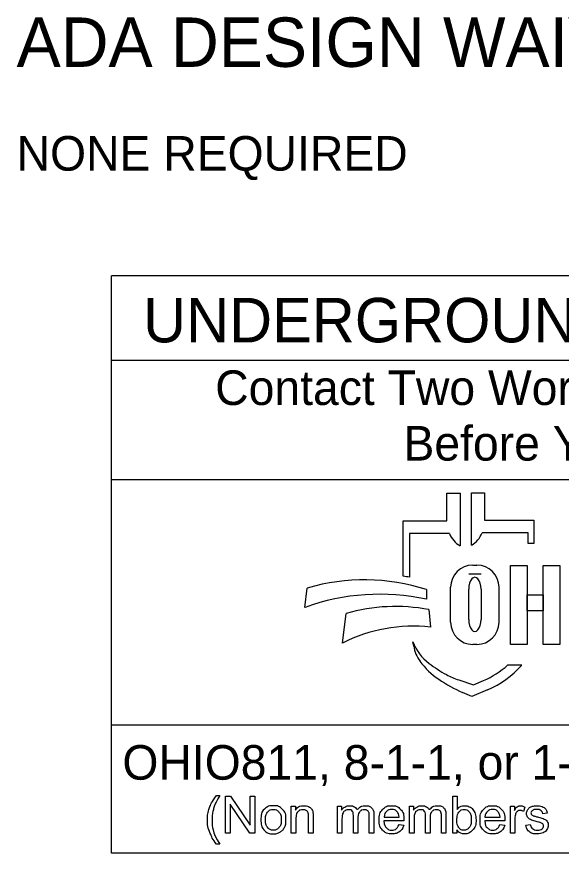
# Model space of a CAD drawing. Extents: x 0 to 64.8, y -5 to 22.
# Drawn here: x 1.995 to 4.196, y 2.143 to 5.529 of the extents above; entities that cross this region are included whole.
import ezdxf

# ---------------------------------------------------------------- set-up
doc = ezdxf.new("R2010")
doc.units = 0
doc.layers.add('SH_Data', color=7, linetype='Continuous')
doc.layers.add('SH_Text', color=7, linetype='Continuous')

msp = doc.modelspace()

# ---------------------------------------------------------------- linework, layer by layer
at = {"layer": 'SH_Data'}
for p, q in [((2.3775, 2.1428), (2.3775, 4.4803)), ((6.6275, 4.4803), (2.3775, 4.4803)), ((2.3775, 4.1387), (6.6275, 4.1387)), ((2.3775, 3.6553), (6.6275, 3.6553)), ((6.6275, 2.6607), (2.3775, 2.6607)), ((6.6275, 2.1428), (2.3775, 2.1428))]:
    msp.add_line(p, q, dxfattribs=at)
at = {"layer": 'SH_Text'}
for p, q in [((3.7335, 3.4883), (3.7335, 3.5998)), ((3.7335, 3.5998), (3.7872, 3.5998)), ((3.7872, 3.5998), (3.7872, 3.3877)), ((3.8329, 3.39), (3.8329, 3.6021)), ((3.8329, 3.6021), (3.8865, 3.6021)), ((3.8865, 3.6021), (3.8865, 3.4906)), ((3.5576, 3.2644), (3.5576, 3.4883)), ((3.5576, 3.4883), (3.7335, 3.4883)), ((3.8865, 3.4906), (4.0857, 3.4906)), ((4.0857, 3.4906), (4.0857, 3.3968)), ((3.5828, 3.4369), (3.5828, 3.26)), ((3.7439, 3.4369), (3.5828, 3.4369)), ((4.0625, 3.4392), (3.8761, 3.4392)), ((4.0625, 3.3968), (4.0625, 3.4392)), ((4.0857, 3.3968), (4.0625, 3.3968)), ((3.8385, 3.3091), (3.8551, 3.3091)), ((3.8718, 3.2721), (3.822, 3.2721)), ((3.7491, 3.0776), (3.7491, 3.2196)), ((3.9445, 3.2196), (3.9445, 3.0776)), ((3.1602, 3.1381), (3.1696, 3.2162)), ((3.6509, 3.2097), (3.6509, 3.1709)), ((3.822, 3.089), (3.822, 3.2114)), ((3.8718, 3.2114), (3.8718, 3.089)), ((3.6608, 3.1291), (3.6671, 3.0582)), ((3.312, 2.9936), (3.3267, 3.1137)), ((3.5997, 2.9807), (3.5967, 2.9986)), ((3.8551, 2.9882), (3.8385, 2.9882)), ((3.98, 2.9048), (4.0375, 2.9048)), ((3.7816, 2.8444), (3.841, 2.8239)), ((3.841, 2.8239), (3.8821, 2.8417)), ((3.835, 2.7769), (3.7976, 2.7934)), ((3.8983, 2.8044), (3.835, 2.7769))]:
    msp.add_line(p, q, dxfattribs=at)
for points in [[(3.991, 3.3081), (4.0589, 3.3081), (4.0589, 2.9881), (3.991, 2.9881)], [(4.1231, 3.3081), (4.1911, 3.3081), (4.1911, 2.9881), (4.1231, 2.9881)], [(4.0589, 3.1882), (4.1231, 3.1882), (4.1231, 3.1242), (4.0589, 3.1242)]]:
    msp.add_lwpolyline(points, close=True, dxfattribs=at)
for points in [[(2.8021, 2.3766), (2.8153, 2.3766)], [(2.8389, 2.2239), (2.8389, 2.3741), (2.8592, 2.3741), (2.9382, 2.2561), (2.9382, 2.3741), (2.9572, 2.3741), (2.9572, 2.2239), (2.9369, 2.2239), (2.8579, 2.3419), (2.8579, 2.2239), (2.8389, 2.2239)], [(3.7743, 2.2239), (3.7573, 2.2239), (3.7573, 2.3741), (3.7757, 2.3741), (3.7757, 2.3206)], [(3.1048, 2.2239), (3.1048, 2.3328), (3.1214, 2.3328), (3.1214, 2.3173)], [(3.2912, 2.2239), (3.2912, 2.3328), (3.3077, 2.3328), (3.3077, 2.3174)], [(3.5826, 2.2239), (3.5826, 2.3328), (3.5991, 2.3328), (3.5991, 2.3174)], [(3.9904, 2.2239), (3.9904, 2.3328), (4.007, 2.3328), (4.007, 2.3163)], [(4.0495, 2.3293), (4.043, 2.3122)], [(4.1394, 2.3046), (4.1213, 2.3022)], [(3.1233, 2.2833), (3.1233, 2.2239), (3.1048, 2.2239)], [(3.1932, 2.2908), (3.1932, 2.2239), (3.1748, 2.2239), (3.1748, 2.2901)], [(3.3097, 2.2803), (3.3097, 2.2239), (3.2912, 2.2239)], [(3.3743, 2.2871), (3.3743, 2.2239), (3.3559, 2.2239), (3.3559, 2.2946)], [(3.4388, 2.2986), (3.4388, 2.2239), (3.4203, 2.2239), (3.4203, 2.2924)], [(3.56, 2.2736), (3.4788, 2.2736)], [(3.4799, 2.2887), (3.5406, 2.2887)], [(3.601, 2.2803), (3.601, 2.2239), (3.5826, 2.2239)], [(3.6657, 2.2871), (3.6657, 2.2239), (3.6473, 2.2239), (3.6473, 2.2946)], [(3.7301, 2.2986), (3.7301, 2.2239), (3.7117, 2.2239), (3.7117, 2.2924)], [(3.968, 2.2736), (3.8868, 2.2736)], [(3.8879, 2.2887), (3.9486, 2.2887)], [(4.0088, 2.2809), (4.0088, 2.2239), (3.9904, 2.2239)], [(3.5404, 2.2591), (3.5595, 2.2567)], [(3.7743, 2.2375), (3.7743, 2.2239)], [(3.9484, 2.2591), (3.9675, 2.2567)], [(4.053, 2.2564), (4.0712, 2.2593)], [(2.8153, 2.1798), (2.8021, 2.1798)]]:
    msp.add_lwpolyline(points, dxfattribs=at)
for centre, radius, start, end in [((3.8353, 3.4736), 0.0985, 201.9296, 240.7469), ((3.7847, 3.476), 0.0985, 299.2531, 338.0704), ((3.8385, 3.2196), 0.0895, 90, 180), ((3.8551, 3.2196), 0.0895, 0, 90), ((3.4295, 2.4554), 0.8191, 79.2074, 81.0007), ((3.3997, 2.4302), 0.8191, 72.1402, 106.3144), ((3.4628, 2.2991), 0.8919, 77.8238, 109.8274), ((3.5267, 2.4094), 0.7322, 79.44, 105.8467), ((3.5987, 2.4262), 0.6357, 83.8248, 116.8021), ((3.8385, 3.0776), 0.0895, 180, 270), ((3.8551, 3.0776), 0.0895, 270, 0), ((3.7841, 3.0707), 0.2008, 201.0457, 232.5314), ((3.741, 3.0048), 0.1433, 189.6817, 216.0884), ((3.8747, 3.1022), 0.3088, 216.0884, 235.7167), ((3.9766, 3.3219), 0.5173, 232.5314, 241.794), ((3.7387, 3.1722), 0.3602, 293.4582, 312.0712), ((3.7387, 3.1722), 0.401, 293.4582, 317.8286), ((4.0412, 3.3465), 0.6044, 235.7167, 246.2325), ((3.8914, 3.1631), 0.3371, 241.794, 250.9821)]:
    msp.add_arc(centre, radius, start, end, dxfattribs=at)
for centre, start_param, end_param in [((3.8469, 3.2114), 4.712389, 7.853982), ((3.8469, 3.089), 1.570796, 4.712389)]:
    msp.add_ellipse(centre, major_axis=(0, 0.0484), ratio=0.514403, start_param=start_param, end_param=end_param, dxfattribs=at)
for points in [[(2.8021, 2.1798), (2.7869, 2.199), (2.7763, 2.2248), (2.7657, 2.2506), (2.7657, 2.2783), (2.7657, 2.3026), (2.7736, 2.325), (2.7829, 2.3509), (2.8021, 2.3766)], [(2.8153, 2.3766), (2.8029, 2.3553), (2.7989, 2.3462), (2.7927, 2.332), (2.7891, 2.3167), (2.7847, 2.2975), (2.7847, 2.2782), (2.7847, 2.2289), (2.8153, 2.1798)], [(2.9814, 2.2783), (2.9814, 2.3085), (2.9981, 2.3231), (3.0122, 2.3352), (3.0323, 2.3352), (3.0547, 2.3352), (3.069, 2.3205), (3.0832, 2.3058), (3.0832, 2.2799), (3.0832, 2.2589), (3.0769, 2.2469), (3.0706, 2.2348), (3.0586, 2.2282), (3.0466, 2.2215), (3.0323, 2.2215), (3.0095, 2.2215), (2.9954, 2.2362), (2.9814, 2.2508), (2.9814, 2.2783)], [(3.0003, 2.2783), (3.0003, 2.2574), (3.0094, 2.247), (3.0185, 2.2366), (3.0323, 2.2366), (3.046, 2.2366), (3.0551, 2.2471), (3.0642, 2.2575), (3.0642, 2.279), (3.0642, 2.2991), (3.0551, 2.3095), (3.0459, 2.3199), (3.0323, 2.3199), (3.0185, 2.3199), (3.0094, 2.3096), (3.0003, 2.2992), (3.0003, 2.2783)], [(3.1214, 2.3173), (3.1334, 2.3352), (3.156, 2.3352), (3.1659, 2.3352), (3.1741, 2.3316), (3.1823, 2.3281), (3.1864, 2.3224), (3.1905, 2.3166), (3.1922, 2.3087), (3.1932, 2.3036), (3.1932, 2.2908)], [(3.1748, 2.2901), (3.1748, 2.3013), (3.1726, 2.3069), (3.1705, 2.3125), (3.165, 2.3158), (3.1595, 2.3191), (3.1521, 2.3191), (3.1404, 2.3191), (3.1318, 2.3117), (3.1233, 2.3042), (3.1233, 2.2833)], [(3.3077, 2.3174), (3.3128, 2.3254), (3.3214, 2.3303), (3.3299, 2.3352), (3.3407, 2.3352), (3.3528, 2.3352), (3.3606, 2.3301), (3.3683, 2.3251), (3.3715, 2.3161), (3.3844, 2.3352), (3.4051, 2.3352), (3.4213, 2.3352), (3.43, 2.3262), (3.4388, 2.3172), (3.4388, 2.2986)], [(3.3559, 2.2946), (3.3559, 2.3069), (3.3514, 2.313), (3.3469, 2.3191), (3.3366, 2.3191), (3.3288, 2.3191), (3.3222, 2.315), (3.3156, 2.311), (3.3126, 2.3031), (3.3097, 2.2952), (3.3097, 2.2803)], [(3.4203, 2.2924), (3.4203, 2.3035), (3.4185, 2.3083), (3.4168, 2.3132), (3.412, 2.3162), (3.4073, 2.3191), (3.401, 2.3191), (3.3895, 2.3191), (3.3819, 2.3115), (3.3743, 2.3039), (3.3743, 2.2871)], [(3.5595, 2.2567), (3.555, 2.24), (3.5428, 2.2307), (3.5306, 2.2215), (3.5117, 2.2215), (3.4878, 2.2215), (3.4738, 2.2362), (3.4598, 2.2509), (3.4598, 2.2774), (3.4598, 2.3049), (3.474, 2.32), (3.4881, 2.3352), (3.5106, 2.3352), (3.5324, 2.3352), (3.5463, 2.3203), (3.5601, 2.3055), (3.5601, 2.2785), (3.5601, 2.2769), (3.56, 2.2736)], [(3.5406, 2.2887), (3.5394, 2.3025), (3.5337, 2.3094), (3.5249, 2.3201), (3.5108, 2.3201), (3.4981, 2.3201), (3.4894, 2.3115), (3.4808, 2.303), (3.4799, 2.2887)], [(3.5991, 2.3174), (3.6042, 2.3254), (3.6127, 2.3303), (3.6212, 2.3352), (3.6321, 2.3352), (3.6442, 2.3352), (3.6519, 2.3301), (3.6597, 2.3251), (3.6628, 2.3161), (3.6758, 2.3352), (3.6965, 2.3352), (3.7127, 2.3352), (3.7214, 2.3262), (3.7301, 2.3172), (3.7301, 2.2986)], [(3.6473, 2.2946), (3.6473, 2.3069), (3.6428, 2.313), (3.6383, 2.3191), (3.628, 2.3191), (3.6202, 2.3191), (3.6136, 2.315), (3.607, 2.311), (3.604, 2.3031), (3.601, 2.2952), (3.601, 2.2803)], [(3.7117, 2.2924), (3.7117, 2.3035), (3.7099, 2.3083), (3.7081, 2.3132), (3.7034, 2.3162), (3.6987, 2.3191), (3.6923, 2.3191), (3.6809, 2.3191), (3.6733, 2.3115), (3.6657, 2.3039), (3.6657, 2.2871)], [(3.7741, 2.2792), (3.7741, 2.2596), (3.7794, 2.2509), (3.7881, 2.2366), (3.8029, 2.2366), (3.815, 2.2366), (3.8238, 2.2471), (3.8326, 2.2576), (3.8326, 2.2784), (3.8326, 2.2998), (3.8241, 2.3099), (3.8157, 2.3201), (3.8038, 2.3201), (3.7917, 2.3201), (3.7829, 2.3096), (3.7741, 2.299), (3.7741, 2.2792)], [(3.7757, 2.3206), (3.7874, 2.3352), (3.8055, 2.3352), (3.8155, 2.3352), (3.8245, 2.3311), (3.8335, 2.3271), (3.8392, 2.3198), (3.845, 2.3124), (3.8483, 2.3021), (3.8516, 2.2918), (3.8516, 2.28), (3.8516, 2.252), (3.8378, 2.2368), (3.8239, 2.2215), (3.8046, 2.2215), (3.7853, 2.2215), (3.7743, 2.2375)], [(3.9675, 2.2567), (3.963, 2.24), (3.9508, 2.2307), (3.9386, 2.2215), (3.9196, 2.2215), (3.8958, 2.2215), (3.8818, 2.2362), (3.8678, 2.2509), (3.8678, 2.2774), (3.8678, 2.3049), (3.882, 2.32), (3.8961, 2.3352), (3.9186, 2.3352), (3.9404, 2.3352), (3.9543, 2.3203), (3.9681, 2.3055), (3.9681, 2.2785), (3.9681, 2.2769), (3.968, 2.2736)], [(3.9486, 2.2887), (3.9474, 2.3025), (3.9417, 2.3094), (3.9328, 2.3201), (3.9188, 2.3201), (3.9061, 2.3201), (3.8974, 2.3115), (3.8888, 2.303), (3.8879, 2.2887)], [(4.007, 2.3163), (4.0133, 2.3278), (4.0187, 2.3315), (4.0241, 2.3352), (4.0305, 2.3352), (4.0398, 2.3352), (4.0495, 2.3293)], [(4.043, 2.3122), (4.0363, 2.3162), (4.0295, 2.3162), (4.0235, 2.3162), (4.0187, 2.3125), (4.0139, 2.3089), (4.0119, 2.3024), (4.0088, 2.2926), (4.0088, 2.2809)], [(4.1213, 2.3022), (4.1201, 2.3106), (4.1142, 2.3153), (4.1083, 2.3201), (4.0975, 2.3201), (4.0848, 2.3201), (4.0794, 2.3159), (4.0739, 2.3116), (4.0739, 2.306), (4.0739, 2.3024), (4.0762, 2.2995), (4.0785, 2.2966), (4.0833, 2.2946), (4.086, 2.2936), (4.0996, 2.2899), (4.1192, 2.2847), (4.1269, 2.2813), (4.1347, 2.278), (4.1391, 2.2717), (4.1435, 2.2653), (4.1435, 2.2559), (4.1435, 2.2467), (4.1381, 2.2386), (4.1327, 2.2304), (4.1226, 2.226), (4.1124, 2.2215), (4.0996, 2.2215), (4.0784, 2.2215), (4.0672, 2.2303), (4.0561, 2.2391), (4.053, 2.2564)], [(4.0712, 2.2593), (4.0727, 2.2483), (4.0798, 2.2425), (4.0868, 2.2366), (4.0995, 2.2366), (4.1122, 2.2366), (4.1184, 2.2418), (4.1245, 2.247), (4.1245, 2.254), (4.1245, 2.2602), (4.1191, 2.2638), (4.1153, 2.2663), (4.1002, 2.2701), (4.0799, 2.2752), (4.072, 2.2789), (4.0642, 2.2827), (4.0601, 2.2893), (4.0561, 2.2959), (4.0561, 2.3038), (4.0561, 2.3111), (4.0594, 2.3173), (4.0628, 2.3235), (4.0685, 2.3276), (4.0728, 2.3308), (4.0803, 2.333), (4.0877, 2.3352), (4.0962, 2.3352), (4.109, 2.3352), (4.1187, 2.3315), (4.1284, 2.3278), (4.133, 2.3215), (4.1377, 2.3152), (4.1394, 2.3046)], [(3.4788, 2.2736), (3.4799, 2.2557), (3.489, 2.2462), (3.4981, 2.2366), (3.5117, 2.2366), (3.5219, 2.2366), (3.5291, 2.242), (3.5362, 2.2473), (3.5404, 2.2591)], [(3.8868, 2.2736), (3.8879, 2.2557), (3.897, 2.2462), (3.9061, 2.2366), (3.9197, 2.2366), (3.9299, 2.2366), (3.937, 2.242), (3.9442, 2.2473), (3.9484, 2.2591)]]:
    msp.add_open_spline(points, degree=3, dxfattribs=at)

# ---------------------------------------------------------------- texts
for s, height, p in [('ADA DESIGN WAIVERS', 0.2, (1.9944, 5.3256)), ('NONE REQUIRED', 0.14, (1.9944, 4.9056)), ('UNDERGROUND UTILITIES', 0.18, (2.5057, 4.2106)), ('Contact Two Working Days', 0.14, (2.7972, 3.9571)), ('Before You Dig', 0.14, (3.5583, 3.7321)), ('OHIO811, 8-1-1, or 1-800-362-2764', 0.14, (2.422, 2.4406))]:
    msp.add_text(s, height=height, dxfattribs=at).set_placement(p)

doc.saveas('drawing.dxf')
